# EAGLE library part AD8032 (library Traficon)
Dual Rail-to-rail I/O amplifier Single supply (2.7V to 5V) or dual supply +/- 5V 80MHz -3dB bandwidth
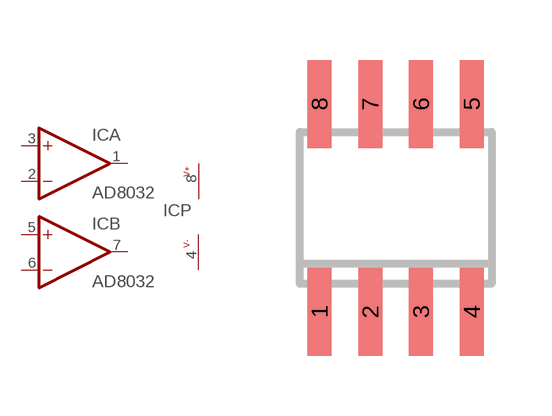
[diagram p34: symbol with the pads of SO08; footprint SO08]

Designator prefix IC; gates A=OPAMP B=OPAMP P=PWR+-

## AD8032  [SO08]
1  A:OUT  out
2  A:-IN  in
3  A:+IN  in
4  P:V-  pas
5  B:+IN  in
6  B:-IN  in
7  B:OUT  out
8  P:V+  pas

## Footprint SO08 (pad centres in mm)
Small Outline Package
smd 0.6 x 2.2: 1 -1.905,-2.6; 2 -0.635,-2.6; 3 0.635,-2.6; 4 1.905,-2.6; 5 1.905,2.6; 6 0.635,2.6; 7 -0.635,2.6; 8 -1.905,2.6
